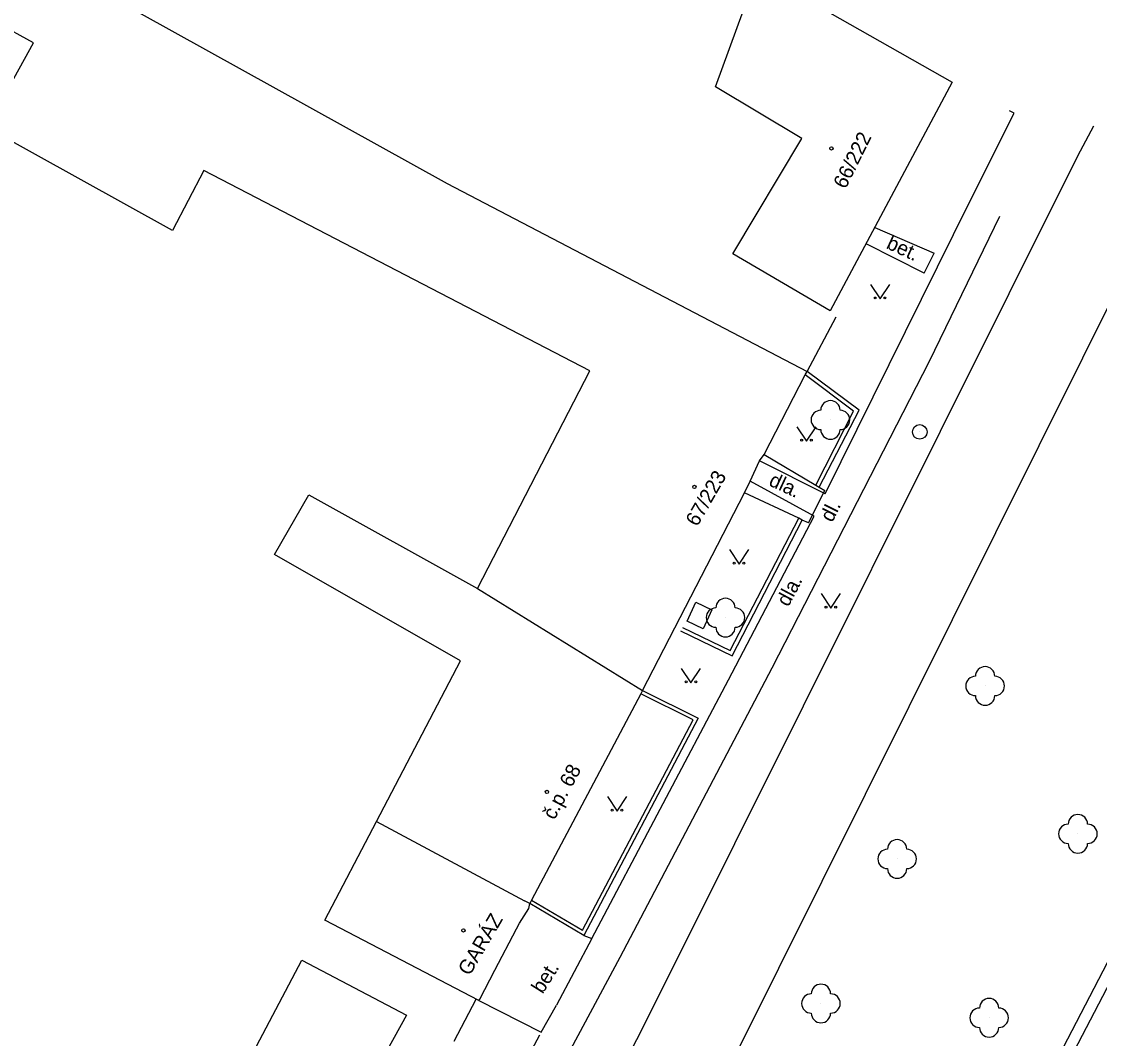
# Model space of a CAD drawing. Extents: x -577457 to -568404, y -1208466 to -1201387.
# Drawn here: x -568736.3 to -568680.5, y -1203707.6 to -1203655 of the extents above; entities that cross this region are included whole.
import ezdxf

# ---------------------------------------------------------------- set-up
doc = ezdxf.new("R2010")
doc.units = 0
for name, color, linetype in [('BUDOVY_MĚŘ', 7, 'Continuous'), ('BUDOVY_NEMĚŘ', 7, 'Continuous'), ('MAP_ZN_BP', 7, 'Continuous'), ('POMOC_POPIS', 7, 'Continuous'), ('ROZHRANÍ_PLOCH', 7, 'Continuous'), ('ZELEŇ', 7, 'Continuous'), ('ZN_BUDOV', 7, 'Continuous'), ('ZN_DOPLŇKOVÉ', 7, 'Continuous'), ('ZN_KULTUR', 7, 'Continuous'), ('Č_POPIS_ORIENT', 7, 'Continuous')]:
    doc.layers.add(name, color=color, linetype=linetype)

msp = doc.modelspace()

# ---------------------------------------------------------------- linework, layer by layer
at = {"layer": 'BUDOVY_MĚŘ'}
for points in [[(-568688.14, -1203658.1), (-568694.44, -1203669.94)], [(-568697.86, -1203677.37), (-568695.73, -1203673.25)], [(-568695.73, -1203673.25), (-568695.64, -1203673.07)], [(-568698.1, -1203677.69), (-568697.86, -1203677.37)], [(-568698.88, -1203679.36), (-568698.58, -1203678.75)], [(-568704.15, -1203689.58), (-568698.88, -1203679.36)], [(-568704.24, -1203689.75), (-568709.89, -1203700.43)], [(-568704.15, -1203689.58), (-568704.24, -1203689.75)], [(-568709.99, -1203700.61), (-568710.25, -1203700.47)], [(-568709.89, -1203700.43), (-568709.99, -1203700.61)], [(-568710.04, -1203700.86), (-568709.99, -1203700.61)], [(-568711.8, -1203704.05), (-568710.67, -1203701.91)], [(-568712.62, -1203705.63), (-568712.56, -1203705.56)]]:
    msp.add_lwpolyline(points, dxfattribs=at)
at = {"layer": 'BUDOVY_NEMĚŘ'}
for points in [[(-568712.69, -1203684.3), (-568706.88, -1203673.04), (-568726.85, -1203662.67), (-568728.46, -1203665.77), (-568738.08, -1203660.45), (-568735.66, -1203656.07), (-568739.43, -1203653.99), (-568737.37, -1203650.52), (-568714.26, -1203663.35), (-568695.64, -1203673.07)], [(-568694.44, -1203669.94), (-568699.48, -1203666.98), (-568695.91, -1203661.02), (-568700.37, -1203658.35), (-568698.21, -1203652.37), (-568688.14, -1203658.1)], [(-568717.91, -1203696.36), (-568713.57, -1203688.05), (-568723.19, -1203682.55), (-568721.42, -1203679.45), (-568712.69, -1203684.3), (-568704.15, -1203689.58)], [(-568720.59, -1203701.47), (-568717.91, -1203696.36)], [(-568717.91, -1203696.36), (-568710.25, -1203700.47)], [(-568712.62, -1203705.63), (-568720.59, -1203701.47)], [(-568727.14, -1203713.71), (-568721.77, -1203703.54), (-568716.36, -1203706.39), (-568717.37, -1203708.2), (-568715, -1203709.53)]]:
    msp.add_lwpolyline(points, dxfattribs=at)
at = {"layer": 'MAP_ZN_BP'}
for radius in [0.375, 0.0005]:
    msp.add_circle((-568689.81, -1203676.201), radius, dxfattribs=at)
at = {"layer": 'ROZHRANÍ_PLOCH'}
for points in [[(-568703.85, -1203717.5), (-568670.15, -1203649.81)], [(-568694.71, -1203679.41), (-568687.24, -1203664.32), (-568684.92, -1203659.7), (-568685.16, -1203659.58)], [(-568733.47, -1203755.98), (-568733.18, -1203756.24), (-568732.84, -1203756.44), (-568732.47, -1203756.56), (-568732.09, -1203756.6), (-568731.7, -1203756.57), (-568731.33, -1203756.46), (-568730.98, -1203756.27), (-568730.69, -1203756.02), (-568730.45, -1203755.71), (-568730.4, -1203755.63), (-568728.91, -1203754.03), (-568713.7, -1203726.12), (-568710.53, -1203719.76), (-568702.93, -1203704.63), (-568681.63, -1203661.91), (-568680.81, -1203660.36)], [(-568685.69, -1203665.05), (-568689.33, -1203672.56)], [(-568692.14, -1203665.62), (-568689.07, -1203666.95)], [(-568689.58, -1203667.98), (-568692.59, -1203666.46)], [(-568689.58, -1203667.98), (-568689.07, -1203666.95)], [(-568689.33, -1203672.56), (-568697.47, -1203688.43)], [(-568694.71, -1203679.41), (-568698.1, -1203677.69)], [(-568697.86, -1203677.37), (-568695.18, -1203678.96)], [(-568695.27, -1203680.56), (-568698.58, -1203678.75)], [(-568696.07, -1203680.67), (-568698.88, -1203679.36)], [(-568695.56, -1203680.91), (-568694.72, -1203679.23)], [(-568695.18, -1203678.96), (-568695.01, -1203679.06)], [(-568695.01, -1203679.06), (-568694.72, -1203679.23)], [(-568706.77, -1203702.41), (-568699.71, -1203689.03), (-568695.27, -1203680.56)], [(-568695.89, -1203680.76), (-568696.07, -1203680.67)], [(-568695.56, -1203680.91), (-568695.89, -1203680.76)], [(-568701.85, -1203686), (-568701.39, -1203685.02)], [(-568701.39, -1203685.02), (-568700.57, -1203685.41)], [(-568700.57, -1203685.41), (-568701.02, -1203686.39)], [(-568701.02, -1203686.39), (-568701.85, -1203686)], [(-568697.47, -1203688.43), (-568705.33, -1203703.4)], [(-568707.19, -1203702.26), (-568706.77, -1203702.41)], [(-568706.77, -1203702.41), (-568708.6, -1203705.87)], [(-568705.33, -1203703.4), (-568721.06, -1203732.74)], [(-568712.62, -1203705.63), (-568709.4, -1203707.27)], [(-568709.4, -1203707.27), (-568708.6, -1203705.87)], [(-568722.28, -1203731.39), (-568709.46, -1203707.4)]]:
    msp.add_lwpolyline(points, dxfattribs=at)
at = {"layer": 'ZELEŇ'}
for points in [[(-568665.52, -1203675.59), (-568684.22, -1203711.57)], [(-568683.72, -1203711.89), (-568664.94, -1203675.85)]]:
    msp.add_lwpolyline(points, dxfattribs=at)
for centre in [(-568694.43, -1203675.58), (-568699.86, -1203685.81), (-568686.43, -1203689.35), (-568681.63, -1203697), (-568690.98, -1203698.3), (-568694.92, -1203705.78), (-568686.22, -1203706.52)]:
    msp.add_circle(centre, 0.0005, dxfattribs=at)
for centre, start, end in [((-568694.43, -1203675.08), 0, 180), ((-568694.93, -1203675.58), 90, 270), ((-568693.93, -1203675.58), 270, 90), ((-568694.43, -1203676.08), 180, 360), ((-568699.86, -1203685.31), 0, 180), ((-568700.36, -1203685.81), 90, 270), ((-568699.36, -1203685.81), 270, 90), ((-568699.86, -1203686.31), 180, 360), ((-568686.93, -1203689.35), 90, 270), ((-568686.43, -1203688.85), 0, 180), ((-568685.93, -1203689.35), 270, 90), ((-568686.43, -1203689.85), 180, 360), ((-568681.63, -1203696.5), 0, 180), ((-568682.13, -1203697), 90, 270), ((-568681.13, -1203697), 270, 90), ((-568691.48, -1203698.3), 90, 270), ((-568690.98, -1203697.8), 0, 180), ((-568690.48, -1203698.3), 270, 90), ((-568681.63, -1203697.5), 180, 360), ((-568690.98, -1203698.8), 180, 360), ((-568694.92, -1203705.28), 0, 180), ((-568695.42, -1203705.78), 90, 270), ((-568694.42, -1203705.78), 270, 90), ((-568686.22, -1203706.02), 0, 180), ((-568686.72, -1203706.52), 90, 270), ((-568685.72, -1203706.52), 270, 90), ((-568694.92, -1203706.28), 180, 360), ((-568686.22, -1203707.02), 180, 360)]:
    msp.add_arc(centre, 0.5, start, end, dxfattribs=at)
at = {"layer": 'ZN_BUDOV'}
for centre in [(-568694.38, -1203661.53), (-568701.47, -1203679.05), (-568709.1, -1203694.83), (-568713.42, -1203702)]:
    msp.add_circle(centre, 0.0875, dxfattribs=at)
at = {"layer": 'ZN_DOPLŇKOVÉ'}
for points in [[(-568695.64, -1203673.07), (-568694.13, -1203670.24)], [(-568695.18, -1203678.96), (-568693.23, -1203675.12), (-568695.73, -1203673.25)], [(-568695.01, -1203679.06), (-568692.95, -1203675.08), (-568695.64, -1203673.07)], [(-568698.58, -1203678.75), (-568698.1, -1203677.69)], [(-568702.18, -1203686.5), (-568699.52, -1203687.79), (-568695.89, -1203680.76)], [(-568702.09, -1203686.32), (-568699.62, -1203687.52), (-568696.07, -1203680.67)], [(-568704.15, -1203689.58), (-568701.28, -1203691.02), (-568707.19, -1203702.26), (-568709.99, -1203700.61)], [(-568709.89, -1203700.43), (-568707.25, -1203701.99), (-568701.54, -1203691.11), (-568704.24, -1203689.75)], [(-568710.51, -1203701.62), (-568710.04, -1203700.86)], [(-568710.67, -1203701.91), (-568710.51, -1203701.62)], [(-568712.56, -1203705.56), (-568711.8, -1203704.05)], [(-568713.89, -1203707.73), (-568712.75, -1203705.56)]]:
    msp.add_lwpolyline(points, dxfattribs=at)
at = {"layer": 'ZN_KULTUR'}
for points in [[(-568692.36, -1203668.57), (-568691.86, -1203669.32), (-568691.36, -1203668.57)], [(-568696.17, -1203675.93), (-568695.67, -1203676.68), (-568695.17, -1203675.93)], [(-568699.66, -1203682.29), (-568699.16, -1203683.04), (-568698.66, -1203682.29)], [(-568694.91, -1203684.57), (-568694.41, -1203685.32), (-568693.91, -1203684.57)], [(-568702.15, -1203688.44), (-568701.65, -1203689.19), (-568701.15, -1203688.44)], [(-568705.97, -1203695.07), (-568705.47, -1203695.82), (-568704.97, -1203695.07)]]:
    msp.add_lwpolyline(points, dxfattribs=at)
for centre in [(-568692.11, -1203669.27), (-568691.61, -1203669.27), (-568695.92, -1203676.63), (-568695.42, -1203676.63), (-568699.41, -1203682.99), (-568698.91, -1203682.99), (-568694.66, -1203685.27), (-568694.16, -1203685.27), (-568701.9, -1203689.14), (-568701.4, -1203689.14), (-568705.72, -1203695.77), (-568705.22, -1203695.77)]:
    msp.add_circle(centre, 0.05, dxfattribs=at)

# ---------------------------------------------------------------- texts
at = {"layer": 'POMOC_POPIS'}
for s, rotation, p in [('bet.', 335.27, (-568691.59, -1203666.68)), ('dla.', 334.98, (-568697.67, -1203678.95)), ('dl.', 63.38, (-568694.34, -1203680.92)), ('dla.', 61.96, (-568696.61, -1203685.29)), ('GARÁZ', 59.59, (-568713.1, -1203704.39)), ('bet.', 57.87, (-568709.32, -1203705.32))]:
    msp.add_text(s, height=0.75, rotation=rotation, dxfattribs=at).set_placement(p)
at = {"layer": 'Č_POPIS_ORIENT'}
for s, rotation, p in [('66/222', 63.53, (-568693.65, -1203663.67)), ('67/223', 60, (-568701.32, -1203681.14)), ('č.p. 68', 62.11, (-568708.71, -1203696.32))]:
    msp.add_text(s, height=0.75, rotation=rotation, dxfattribs=at).set_placement(p)

doc.saveas('drawing.dxf')
